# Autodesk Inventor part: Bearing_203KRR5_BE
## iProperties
Created: 2008-11
Part Number: Bearing_203KRR5_BE
Document SubType Name: Modeling
Designer: ETUDIANT
Author: ETUDIANT
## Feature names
1. Révolution1 [Revolution]
